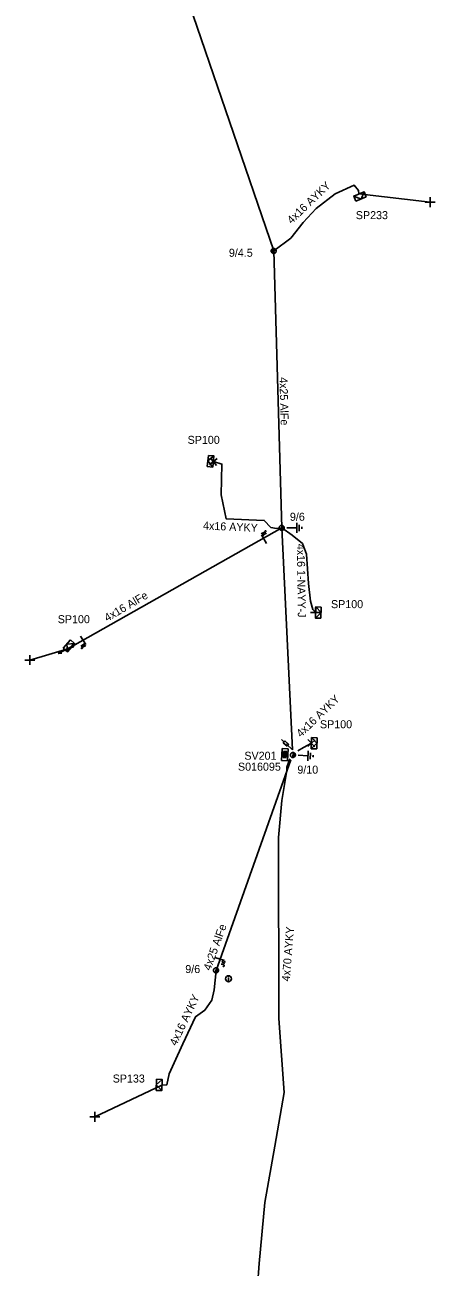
# Model space of a CAD drawing. Extents: x -717562 to -713845, y -1151196 to -1143903.
# Drawn here: x -716921.3 to -716870.1, y -1144824.8 to -1144669.5 of the extents above; entities that cross this region are included whole.
import ezdxf

# ---------------------------------------------------------------- set-up
doc = ezdxf.new("R2010")
doc.units = 0
for name, color, linetype in [('Vrstva 1', 7, 'Continuous'), ('Vrstva 10', 7, 'Continuous'), ('Vrstva 12', 7, 'Continuous'), ('Vrstva 13', 7, 'Continuous'), ('Vrstva 14', 7, 'Continuous'), ('Vrstva 15', 7, 'Continuous'), ('Vrstva 16', 7, 'Continuous'), ('Vrstva 18', 7, 'Continuous'), ('Vrstva 2', 7, 'Continuous'), ('Vrstva 28', 7, 'Continuous'), ('Vrstva 29', 7, 'Continuous'), ('Vrstva 30', 7, 'Continuous'), ('Vrstva 31', 7, 'Continuous'), ('Vrstva 33', 7, 'Continuous'), ('Vrstva 34', 7, 'Continuous'), ('Vrstva 36', 7, 'Continuous'), ('Vrstva 4', 7, 'Continuous'), ('Vrstva 5', 7, 'Continuous'), ('Vrstva 52', 7, 'Continuous'), ('Vrstva 53', 7, 'Continuous'), ('Vrstva 54', 7, 'Continuous'), ('Vrstva 59', 7, 'Continuous'), ('Vrstva 6', 7, 'Continuous'), ('Vrstva 8', 7, 'Continuous'), ('Vrstva 9', 7, 'Continuous')]:
    doc.layers.add(name, color=color, linetype=linetype)

# ---------------------------------------------------------------- blocks, each defined once
blk = doc.blocks.new('NN440')
at = {"layer": 'Vrstva 2'}
for points in [[(0.63, 0), (0.63, 0.06), (0.62, 0.13), (0.6, 0.19), (0.58, 0.25), (0.55, 0.31), (0.51, 0.37), (0.47, 0.42), (0.42, 0.46), (0.37, 0.51), (0.32, 0.54), (0.26, 0.57), (0.2, 0.59), (0.13, 0.61), (0.07, 0.62), (0, 0.63), (-0.06, 0.62), (-0.13, 0.61), (-0.19, 0.59), (-0.26, 0.57), (-0.31, 0.54), (-0.37, 0.51), (-0.42, 0.46), (-0.47, 0.42), (-0.51, 0.37), (-0.54, 0.31), (-0.57, 0.25), (-0.6, 0.19), (-0.62, 0.13), (-0.63, 0.06), (-0.63, 0), (-0.63, -0.07), (-0.62, -0.14), (-0.6, -0.2), (-0.57, -0.26), (-0.54, -0.32), (-0.51, -0.37), (-0.47, -0.43), (-0.42, -0.47), (-0.37, -0.51), (-0.31, -0.55), (-0.26, -0.58), (-0.19, -0.6), (-0.13, -0.62), (-0.06, -0.63), (0, -0.63), (0.07, -0.63), (0.13, -0.62), (0.2, -0.6), (0.26, -0.58), (0.32, -0.55), (0.37, -0.51), (0.42, -0.47), (0.47, -0.43), (0.51, -0.37), (0.55, -0.32), (0.58, -0.26), (0.6, -0.2), (0.62, -0.14), (0.63, -0.07), (0.63, 0)], [(-0.63, 0), (0.63, 0)], [(-0.6, -0.18), (0.57, -0.18)], [(-0.51, -0.32), (0.5, -0.32)], [(-0.37, -0.47), (0.35, -0.47)]]:
    blk.add_lwpolyline(points, dxfattribs=at)
blk = doc.blocks.new('NN560')
at = {"layer": 'Vrstva 2'}
for points in [[(2, 0), (1.59, 0.14)], [(0, 0), (2, 0)], [(2, 0), (1.59, -0.13)]]:
    blk.add_lwpolyline(points, dxfattribs=at)
blk = doc.blocks.new('NN840')
at = {"layer": 'Vrstva 15'}
for points in [[(0, 0.62), (0, -0.63)], [(-0.75, -0.71), (-0.75, -0.66)], [(-0.73, -0.76), (-0.75, -0.71)], [(-0.66, -0.8), (-0.73, -0.76)], [(-0.63, -0.8), (-0.66, -0.8)], [(-0.56, -0.76), (-0.63, -0.8)], [(-0.54, -0.71), (-0.56, -0.76)], [(-0.54, -0.38), (-0.54, -0.71)], [(-0.33, -0.38), (-0.33, -0.8)], [(-0.33, -0.64), (-0.13, -0.38)], [(-0.26, -0.56), (-0.09, -0.8)]]:
    blk.add_lwpolyline(points, dxfattribs=at)
blk = doc.blocks.new('NN770')
at = {"layer": 'Vrstva 10'}
for p, q in [((0, 0.19), (0, 0.26)), ((0, -0.28), (0, 0.11))]:
    blk.add_line(p, q, dxfattribs=at)
blk.add_circle((0, -0.01), 0.375, dxfattribs=at)
blk = doc.blocks.new('NN800')
at = {"layer": 'Vrstva 1'}
for points in [[(-0.44, 0.44), (0.44, -0.44)], [(-0.44, -0.44), (0.44, 0.44)]]:
    blk.add_lwpolyline(points, dxfattribs=at)
blk = doc.blocks.new('NN820')
at = {"layer": 'Vrstva 13'}
for points in [[(0, 0), (0, -1.05)], [(-0.16, -0.81), (0.16, -0.81)], [(-0.16, -1.47), (-0.16, -0.81)], [(0.16, -1.47), (-0.16, -1.47)], [(0, -1.05), (-0.06, -0.93)], [(0, -1.05), (0.06, -0.93)], [(0, -1.47), (0, -1.87)], [(0.16, -0.81), (0.16, -1.47)]]:
    blk.add_lwpolyline(points, dxfattribs=at)
blk = doc.blocks.new('NN620')
at = {"layer": 'Vrstva 8'}
for points in [[(0.75, 0), (-0.75, 0)], [(-0.75, 0), (-0.75, -0.75)], [(0.75, -0.75), (0.75, 0)], [(-0.75, -0.75), (0.75, -0.75)], [(0.37, -0.18), (-0.38, -0.18)], [(-0.38, -0.18), (-0.38, -0.56)], [(-0.38, -0.56), (0.37, -0.56)], [(0.32, -0.23), (-0.33, -0.23)], [(-0.33, -0.23), (-0.33, -0.51)], [(-0.33, -0.51), (0.32, -0.51)], [(0.27, -0.27), (-0.28, -0.27)], [(-0.28, -0.27), (-0.28, -0.46)], [(-0.28, -0.46), (0.27, -0.46)], [(0.23, -0.32), (-0.23, -0.32)], [(-0.23, -0.32), (-0.23, -0.42)], [(-0.23, -0.42), (0.23, -0.42)], [(-0.19, -0.37), (0.19, -0.37)], [(0.23, -0.42), (0.23, -0.32)], [(0.27, -0.46), (0.27, -0.27)], [(0.32, -0.51), (0.32, -0.23)], [(0.37, -0.56), (0.37, -0.18)]]:
    blk.add_lwpolyline(points, dxfattribs=at)
blk = doc.blocks.new('NN630')
at = {"layer": 'Vrstva 9'}
for points in [[(0, -0.7), (-0.7, 0)], [(-0.7, -0.7), (-0.7, 0), (0.7, 0), (0.7, -0.7)], [(-0.7, -0.7), (0.7, -0.7)], [(0, -0.7), (0.7, 0)]]:
    blk.add_lwpolyline(points, dxfattribs=at)
blk = doc.blocks.new('NN810')
at = {"layer": 'Vrstva 14'}
for points in [[(0, -0.64), (0, -1.89)], [(0.63, -1.89), (-0.62, -1.89)], [(0.39, -2.2), (-0.4, -2.2)], [(0, -2.52), (-0.12, -2.52)], [(0.14, -2.52), (0, -2.52)]]:
    blk.add_lwpolyline(points, dxfattribs=at)
blk = doc.blocks.new('NN500')
at = {"layer": 'Vrstva 2'}
for points in [[(0, -0.24), (0.02, -0.23), (0.05, -0.23), (0.07, -0.22), (0.09, -0.22), (0.12, -0.2), (0.14, -0.19), (0.16, -0.18), (0.17, -0.16), (0.19, -0.14), (0.2, -0.12), (0.21, -0.1), (0.22, -0.07), (0.23, -0.05), (0.23, -0.02), (0.23, 0), (0.23, 0.02), (0.23, 0.05), (0.22, 0.07), (0.21, 0.1), (0.2, 0.12), (0.19, 0.14), (0.17, 0.16), (0.16, 0.17), (0.14, 0.19), (0.12, 0.2), (0.09, 0.21), (0.07, 0.22), (0.05, 0.23), (0.02, 0.23), (0, 0.23), (-0.03, 0.23), (-0.05, 0.23), (-0.07, 0.22), (-0.1, 0.21), (-0.12, 0.2), (-0.14, 0.19), (-0.16, 0.17), (-0.18, 0.16), (-0.19, 0.14), (-0.2, 0.12), (-0.22, 0.1), (-0.22, 0.07), (-0.23, 0.05), (-0.23, 0.02), (-0.24, 0), (-0.23, -0.02), (-0.23, -0.05), (-0.22, -0.07), (-0.22, -0.1), (-0.2, -0.12), (-0.19, -0.14), (-0.18, -0.16), (-0.16, -0.18), (-0.14, -0.19), (-0.12, -0.2), (-0.1, -0.22), (-0.07, -0.22), (-0.05, -0.23), (-0.03, -0.23), (0, -0.24)], [(0, -0.24), (0.02, -0.23), (0.05, -0.23), (0.07, -0.22), (0.09, -0.22), (0.12, -0.2), (0.14, -0.19), (0.16, -0.18), (0.17, -0.16), (0.19, -0.14), (0.2, -0.12), (0.21, -0.1), (0.22, -0.07), (0.23, -0.05), (0.23, -0.02), (0.23, 0), (0.23, 0.02), (0.23, 0.05), (0.22, 0.07), (0.21, 0.1), (0.2, 0.12), (0.19, 0.14), (0.17, 0.16), (0.16, 0.17), (0.14, 0.19), (0.12, 0.2), (0.09, 0.21), (0.07, 0.22), (0.05, 0.23), (0.02, 0.23), (0, 0.23), (-0.03, 0.23), (-0.05, 0.23), (-0.07, 0.22), (-0.1, 0.21), (-0.12, 0.2), (-0.14, 0.19), (-0.16, 0.17), (-0.18, 0.16), (-0.19, 0.14), (-0.2, 0.12), (-0.22, 0.1), (-0.22, 0.07), (-0.23, 0.05), (-0.23, 0.02), (-0.24, 0), (-0.23, -0.02), (-0.23, -0.05), (-0.22, -0.07), (-0.22, -0.1), (-0.2, -0.12), (-0.19, -0.14), (-0.18, -0.16), (-0.16, -0.18), (-0.14, -0.19), (-0.12, -0.2), (-0.1, -0.22), (-0.07, -0.22), (-0.05, -0.23), (-0.03, -0.23), (0, -0.24)], [(0, -0.21), (0.02, -0.2), (0.04, -0.2), (0.06, -0.2), (0.08, -0.19), (0.1, -0.18), (0.12, -0.17), (0.14, -0.15), (0.15, -0.14), (0.16, -0.12), (0.18, -0.1), (0.19, -0.08), (0.19, -0.06), (0.2, -0.04), (0.2, -0.02), (0.2, 0), (0.2, 0.02), (0.2, 0.04), (0.19, 0.06), (0.19, 0.08), (0.18, 0.1), (0.16, 0.12), (0.15, 0.14), (0.14, 0.15), (0.12, 0.17), (0.1, 0.18), (0.08, 0.19), (0.06, 0.19), (0.04, 0.2), (0.02, 0.2), (0, 0.2), (-0.02, 0.2), (-0.04, 0.2), (-0.06, 0.19), (-0.08, 0.19), (-0.1, 0.18), (-0.12, 0.17), (-0.14, 0.15), (-0.15, 0.14), (-0.17, 0.12), (-0.18, 0.1), (-0.19, 0.08), (-0.2, 0.06), (-0.2, 0.04), (-0.21, 0.02), (-0.21, 0), (-0.21, -0.02), (-0.2, -0.04), (-0.2, -0.06), (-0.19, -0.08), (-0.18, -0.1), (-0.17, -0.12), (-0.15, -0.14), (-0.14, -0.15), (-0.12, -0.17), (-0.1, -0.18), (-0.08, -0.19), (-0.06, -0.2), (-0.04, -0.2), (-0.02, -0.2), (0, -0.21)], [(0, -0.18), (0.02, -0.18), (0.04, -0.17), (0.05, -0.17), (0.07, -0.16), (0.09, -0.15), (0.1, -0.14), (0.12, -0.13), (0.13, -0.12), (0.14, -0.1), (0.15, -0.09), (0.16, -0.07), (0.17, -0.05), (0.17, -0.04), (0.17, -0.02), (0.17, 0), (0.17, 0.02), (0.17, 0.04), (0.17, 0.05), (0.16, 0.07), (0.15, 0.09), (0.14, 0.1), (0.13, 0.12), (0.12, 0.13), (0.1, 0.14), (0.09, 0.15), (0.07, 0.16), (0.05, 0.17), (0.04, 0.17), (0.02, 0.17), (0, 0.18), (-0.02, 0.17), (-0.04, 0.17), (-0.06, 0.17), (-0.07, 0.16), (-0.09, 0.15), (-0.1, 0.14), (-0.12, 0.13), (-0.13, 0.12), (-0.14, 0.1), (-0.15, 0.09), (-0.16, 0.07), (-0.17, 0.05), (-0.17, 0.04), (-0.18, 0.02), (-0.18, 0), (-0.18, -0.02), (-0.17, -0.04), (-0.17, -0.05), (-0.16, -0.07), (-0.15, -0.09), (-0.14, -0.1), (-0.13, -0.12), (-0.12, -0.13), (-0.1, -0.14), (-0.09, -0.15), (-0.07, -0.16), (-0.06, -0.17), (-0.04, -0.17), (-0.02, -0.18), (0, -0.18)], [(0, -0.15), (0.01, -0.15), (0.03, -0.14), (0.04, -0.14), (0.06, -0.13), (0.07, -0.13), (0.08, -0.12), (0.1, -0.11), (0.11, -0.1), (0.12, -0.09), (0.13, -0.07), (0.13, -0.06), (0.14, -0.05), (0.14, -0.03), (0.14, -0.02), (0.14, 0), (0.14, 0.01), (0.14, 0.03), (0.14, 0.04), (0.13, 0.06), (0.13, 0.07), (0.12, 0.09), (0.11, 0.1), (0.1, 0.11), (0.08, 0.12), (0.07, 0.13), (0.06, 0.13), (0.04, 0.14), (0.03, 0.14), (0.01, 0.14), (0, 0.15), (-0.02, 0.14), (-0.03, 0.14), (-0.05, 0.14), (-0.06, 0.13), (-0.07, 0.13), (-0.09, 0.12), (-0.1, 0.11), (-0.11, 0.1), (-0.12, 0.09), (-0.13, 0.07), (-0.13, 0.06), (-0.14, 0.04), (-0.14, 0.03), (-0.15, 0.01), (-0.15, 0), (-0.15, -0.02), (-0.14, -0.03), (-0.14, -0.05), (-0.13, -0.06), (-0.13, -0.07), (-0.12, -0.09), (-0.11, -0.1), (-0.1, -0.11), (-0.09, -0.12), (-0.07, -0.13), (-0.06, -0.13), (-0.05, -0.14), (-0.03, -0.14), (-0.02, -0.15), (0, -0.15)], [(0, -0.12), (0.01, -0.12), (0.02, -0.11), (0.03, -0.11), (0.05, -0.11), (0.06, -0.1), (0.07, -0.09), (0.08, -0.09), (0.09, -0.08), (0.09, -0.07), (0.1, -0.06), (0.11, -0.05), (0.11, -0.04), (0.11, -0.02), (0.11, -0.01), (0.12, 0), (0.11, 0.01), (0.11, 0.02), (0.11, 0.04), (0.11, 0.05), (0.1, 0.06), (0.09, 0.07), (0.09, 0.08), (0.08, 0.09), (0.07, 0.09), (0.06, 0.1), (0.05, 0.11), (0.03, 0.11), (0.02, 0.11), (0.01, 0.12), (0, 0.12), (-0.01, 0.12), (-0.03, 0.11), (-0.04, 0.11), (-0.05, 0.11), (-0.06, 0.1), (-0.07, 0.09), (-0.08, 0.09), (-0.09, 0.08), (-0.1, 0.07), (-0.1, 0.06), (-0.11, 0.05), (-0.11, 0.04), (-0.12, 0.02), (-0.12, 0.01), (-0.12, 0), (-0.12, -0.01), (-0.12, -0.02), (-0.11, -0.04), (-0.11, -0.05), (-0.1, -0.06), (-0.1, -0.07), (-0.09, -0.08), (-0.08, -0.09), (-0.07, -0.09), (-0.06, -0.1), (-0.05, -0.11), (-0.04, -0.11), (-0.03, -0.11), (-0.01, -0.12), (0, -0.12)], [(0, -0.09), (0.01, -0.09), (0.02, -0.09), (0.03, -0.08), (0.03, -0.08), (0.04, -0.08), (0.05, -0.07), (0.06, -0.07), (0.06, -0.06), (0.07, -0.05), (0.07, -0.04), (0.08, -0.04), (0.08, -0.03), (0.08, -0.02), (0.09, -0.01), (0.09, 0), (0.09, 0.01), (0.08, 0.02), (0.08, 0.03), (0.08, 0.03), (0.07, 0.04), (0.07, 0.05), (0.06, 0.06), (0.06, 0.06), (0.05, 0.07), (0.04, 0.07), (0.03, 0.08), (0.03, 0.08), (0.02, 0.08), (0.01, 0.09), (0, 0.09), (-0.01, 0.09), (-0.02, 0.08), (-0.03, 0.08), (-0.04, 0.08), (-0.04, 0.07), (-0.05, 0.07), (-0.06, 0.06), (-0.07, 0.06), (-0.07, 0.05), (-0.08, 0.04), (-0.08, 0.03), (-0.08, 0.03), (-0.09, 0.02), (-0.09, 0.01), (-0.09, 0), (-0.09, -0.01), (-0.09, -0.02), (-0.08, -0.03), (-0.08, -0.04), (-0.08, -0.04), (-0.07, -0.05), (-0.07, -0.06), (-0.06, -0.07), (-0.05, -0.07), (-0.04, -0.08), (-0.04, -0.08), (-0.03, -0.08), (-0.02, -0.09), (-0.01, -0.09), (0, -0.09)], [(0, -0.06), (0, -0.06), (0.01, -0.06), (0.02, -0.05), (0.02, -0.05), (0.03, -0.05), (0.03, -0.05), (0.04, -0.04), (0.04, -0.04), (0.05, -0.03), (0.05, -0.03), (0.05, -0.02), (0.05, -0.02), (0.05, -0.01), (0.06, -0.01), (0.06, 0), (0.06, 0.01), (0.05, 0.01), (0.05, 0.02), (0.05, 0.02), (0.05, 0.03), (0.05, 0.03), (0.04, 0.04), (0.04, 0.04), (0.03, 0.05), (0.03, 0.05), (0.02, 0.05), (0.02, 0.05), (0.01, 0.06), (0, 0.06), (0, 0.06), (-0.01, 0.06), (-0.01, 0.06), (-0.02, 0.05), (-0.02, 0.05), (-0.03, 0.05), (-0.03, 0.05), (-0.04, 0.04), (-0.04, 0.04), (-0.05, 0.03), (-0.05, 0.03), (-0.05, 0.02), (-0.06, 0.02), (-0.06, 0.01), (-0.06, 0.01), (-0.06, 0), (-0.06, -0.01), (-0.06, -0.01), (-0.06, -0.02), (-0.05, -0.02), (-0.05, -0.03), (-0.05, -0.03), (-0.04, -0.04), (-0.04, -0.04), (-0.03, -0.05), (-0.03, -0.05), (-0.02, -0.05), (-0.02, -0.05), (-0.01, -0.06), (-0.01, -0.06), (0, -0.06)], [(0, -0.03), (0, -0.03), (0, -0.03), (0.01, -0.03), (0.01, -0.03), (0.01, -0.02), (0.02, -0.02), (0.02, -0.02), (0.02, -0.02), (0.02, -0.02), (0.02, -0.01), (0.02, -0.01), (0.03, -0.01), (0.03, -0.01), (0.03, 0), (0.03, 0), (0.03, 0), (0.03, 0.01), (0.03, 0.01), (0.02, 0.01), (0.02, 0.01), (0.02, 0.02), (0.02, 0.02), (0.02, 0.02), (0.02, 0.02), (0.01, 0.02), (0.01, 0.02), (0.01, 0.03), (0, 0.03), (0, 0.03), (0, 0.03), (0, 0.03), (-0.01, 0.03), (-0.01, 0.03), (-0.01, 0.02), (-0.02, 0.02), (-0.02, 0.02), (-0.02, 0.02), (-0.02, 0.02), (-0.02, 0.02), (-0.03, 0.01), (-0.03, 0.01), (-0.03, 0.01), (-0.03, 0.01), (-0.03, 0), (-0.03, 0), (-0.03, 0), (-0.03, -0.01), (-0.03, -0.01), (-0.03, -0.01), (-0.03, -0.01), (-0.02, -0.02), (-0.02, -0.02), (-0.02, -0.02), (-0.02, -0.02), (-0.02, -0.02), (-0.01, -0.03), (-0.01, -0.03), (-0.01, -0.03), (0, -0.03), (0, -0.03)], [(0.23, 0), (0.7, 0)]]:
    blk.add_lwpolyline(points, dxfattribs=at)

msp = doc.modelspace()

# ---------------------------------------------------------------- linework, layer by layer
at = {"layer": 'Vrstva 1'}
for points in [[(-716887.86, -1144760.11), (-716889.23, -1144732.39), (-716890.23, -1144697.78), (-716901.29, -1144665.4)], [(-716888.07, -1144761.39), (-716897.43, -1144787.68)]]:
    msp.add_lwpolyline(points, dxfattribs=at)
at = {"layer": 'Vrstva 4'}
msp.add_lwpolyline([(-716889.23, -1144732.39), (-716915.35, -1144747.19), (-716915.54, -1144747.36)], dxfattribs=at)
at = {"layer": 'Vrstva 5'}
msp.add_lwpolyline([(-716888.22, -1144761.25), (-716888.58, -1144762.29), (-716888.59, -1144762.7), (-716889.19, -1144766.45), (-716889.61, -1144771.07), (-716889.58, -1144793.7), (-716888.91, -1144802.96), (-716890.08, -1144809.67), (-716891.32, -1144816.71), (-716892.04, -1144824.33), (-716892.47, -1144829.96), (-716892.58, -1144836.07), (-716892.26, -1144836.54), (-716892.03, -1144836.56)], dxfattribs=at)
at = {"layer": 'Vrstva 52'}
for points in [[(-716890.23, -1144697.78), (-716888.08, -1144696.17), (-716886.55, -1144694.24), (-716884.93, -1144692.48), (-716882.56, -1144690.63), (-716880.19, -1144689.56), (-716879.64, -1144690.23), (-716879.59, -1144690.66)], [(-716889.23, -1144732.39), (-716889.89, -1144732.46), (-716890.58, -1144732.35), (-716891.4, -1144731.45), (-716896.18, -1144731.24), (-716896.78, -1144728.25), (-716896.69, -1144724.42), (-716897.76, -1144724.1)], [(-716889.23, -1144732.39), (-716887.91, -1144733.29), (-716886.63, -1144734.35), (-716886.11, -1144735.67), (-716885.87, -1144739.34), (-716885.61, -1144741.54), (-716885.34, -1144742.58), (-716885, -1144742.96)], [(-716887.23, -1144760.23), (-716886.5, -1144759.83), (-716885.52, -1144759.29)], [(-716897.43, -1144787.68), (-716897.66, -1144790.1), (-716897.94, -1144791.39), (-716898.84, -1144792.64), (-716899.98, -1144793.48), (-716901.59, -1144796.85), (-716902.67, -1144799.24), (-716903.28, -1144800.61), (-716903.57, -1144801.98), (-716904.19, -1144802.01)]]:
    msp.add_lwpolyline(points, dxfattribs=at)
at = {"layer": 'Vrstva 59'}
for points in [[(-716879.59, -1144690.66), (-716870.69, -1144691.69)], [(-716915.54, -1144747.36), (-716920.68, -1144748.9)], [(-716904.19, -1144802.01), (-716912.56, -1144805.98)]]:
    msp.add_lwpolyline(points, dxfattribs=at)

# ---------------------------------------------------------------- block references
at = {"layer": 'Vrstva 13'}
for name, p, xscale, yscale, rotation in [('NN440', (-716890.23, -1144697.78), 0.49999999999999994, 0.5000000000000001, -70.23763893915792), ('NN440', (-716889.23, -1144732.39), 0.5, 0.5, 86.51269172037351), ('NN500', (-716915.35, -1144747.19), 0.5, 0.5, 90), ('NN440', (-716887.83, -1144760.77), 0.5, 0.5, 86.5126916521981), ('NN440', (-716897.43, -1144787.68), 0.5, 0.5, 73.67484445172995)]:
    msp.add_blockref(name, p, dxfattribs=dict(at, xscale=xscale, yscale=yscale, rotation=rotation))
at = {"layer": 'Vrstva 13', "rotation": -152.81511502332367}
msp.add_blockref('NN560', (-716915.35, -1144747.19), dxfattribs=at)
at = {"layer": 'Vrstva 15'}
for p, rotation in [((-716889.23, -1144732.39), 90), ((-716887.83, -1144760.77), 86.55561389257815)]:
    msp.add_blockref('NN810', p, dxfattribs=dict(at, rotation=rotation))
at = {"layer": 'Vrstva 16', "rotation": -132.55930262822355}
msp.add_blockref('NN820', (-716887.86, -1144760.11), dxfattribs=at)
at = {"layer": 'Vrstva 18'}
for p, rotation in [((-716891.44, -1144733.8), -148.584513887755), ((-716914.02, -1144746.44), 31.415486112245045), ((-716896.99, -1144786.27), 73.67484445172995)]:
    msp.add_blockref('NN840', p, dxfattribs=dict(at, rotation=rotation))
at = {"layer": 'Vrstva 28', "rotation": -93.48700000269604}
msp.add_blockref('NN620', (-716888.45, -1144760.74), dxfattribs=at)
at = {"layer": 'Vrstva 31'}
for p, rotation in [((-716879.59, -1144690.66), 22.743552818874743), ((-716897.76, -1144724.1), -95.80638333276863), ((-716885, -1144742.96), 88.2652444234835), ((-716915.54, -1144747.36), -130.2732499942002), ((-716885.52, -1144759.29), 88.2652444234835), ((-716904.19, -1144802.01), -92.24033609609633)]:
    msp.add_blockref('NN630', p, dxfattribs=dict(at, rotation=rotation))
at = {"layer": 'Vrstva 34'}
for p, rotation in [((-716870.69, -1144691.69), 45), ((-716897.76, -1144724.1), -95.80638331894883), ((-716885, -1144742.96), 45), ((-716920.68, -1144748.9), 45), ((-716885.52, -1144759.29), 88.2652444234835), ((-716912.56, -1144805.98), 45)]:
    msp.add_blockref('NN800', p, dxfattribs=dict(at, rotation=rotation))
at = {"layer": 'Vrstva 36'}
msp.add_blockref('NN770', (-716895.87, -1144788.72), dxfattribs=at)

# ---------------------------------------------------------------- texts
at = {"layer": 'Vrstva 12'}
for s, p in [('9/4.5', (-716895.82, -1144698.51)), ('9/6', (-716888.2, -1144731.5)), ('9/10', (-716887.27, -1144763.1)), ('9/6', (-716901.27, -1144788.02))]:
    msp.add_text(s, height=1, dxfattribs=at).set_placement(p)
at = {"layer": 'Vrstva 2'}
for rotation, p in [(271.571, (-716889.51, -1144713.57)), (70.274, (-716898.12, -1144787.78))]:
    msp.add_text('4x25 AlFe', height=1, rotation=rotation, dxfattribs=at).set_placement(p)
at = {"layer": 'Vrstva 29'}
msp.add_text('S016095', height=1, dxfattribs=at).set_placement((-716894.69, -1144762.73))
at = {"layer": 'Vrstva 30'}
msp.add_text('SV201', height=1, dxfattribs=at).set_placement((-716893.89, -1144761.36))
at = {"layer": 'Vrstva 33'}
for s, p in [('SP233', (-716879.97, -1144693.81)), ('SP100', (-716900.98, -1144721.89)), ('SP100', (-716883.07, -1144742.42)), ('SP100', (-716917.2, -1144744.3)), ('SP100', (-716884.45, -1144757.43)), ('SP133', (-716910.34, -1144801.7))]:
    msp.add_text(s, height=1, dxfattribs=at).set_placement(p)
at = {"layer": 'Vrstva 53'}
msp.add_text('4x16 AlFe', height=1, rotation=30.438, dxfattribs=at).set_placement((-716911.02, -1144744.15))
at = {"layer": 'Vrstva 54'}
for s, rotation, p in [('4x16 AYKY', 43.669, (-716887.99, -1144694.47)), ('4x16 AYKY', 357.484, (-716899.07, -1144732.59)), ('4x16 1-NAYY-J', 270.809, (-716887.34, -1144734.39)), ('4x16 AYKY', 43.931, (-716886.83, -1144758.63)), ('4x16 AYKY', 64.592, (-716902.39, -1144797.19))]:
    msp.add_text(s, height=1, rotation=rotation, dxfattribs=at).set_placement(p)
at = {"layer": 'Vrstva 6'}
msp.add_text('4x70 AYKY', height=1, rotation=85.413, dxfattribs=at).set_placement((-716888.22, -1144789.09))

doc.saveas('drawing.dxf')
